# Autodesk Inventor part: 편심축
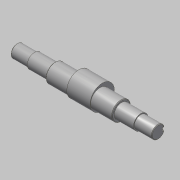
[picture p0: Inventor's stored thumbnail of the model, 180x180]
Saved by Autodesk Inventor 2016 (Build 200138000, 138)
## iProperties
Created: 2015-10
Part Number: 편심축
Document SubType Name: Modeling
Designer: mdu
Density: 7.86 g/cm^3
Material: 강철, 연강
Mass: 1327.93 g
Surface Area: 248.524 cm^2
Volume: 168.947 cm^3
Appearance: 강철
Author: mdu
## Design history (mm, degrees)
sketch "스케치1"
  geometry: L1 (-20.5, -41.331)-(-20.5, 32.669) reference; L2 (7.5, -30.031)-(7.5, 21.369) reference; L3 (135.5, -30.331)-(135.5, 21.669) reference; L4 (121.5, 21.369)-(121.5, -30.031) reference; L5 (184.5, -4.331)-(-57.5, -4.331); L6 (184.5, -4.331)-(184.5, 6.669); L7 (154.5, 8.169)-(121.5, 8.169); L8 (121.5, 8.169)-(121.5, 11.669); L9 (121.5, 11.669)-(7.5, 11.669); L10 (7.5, 11.669)-(7.5, 8.169); L11 (7.5, 8.169)-(-27.5, 8.169); L12 (-27.5, 8.169)-(-27.5, 6.669); L13 (-27.5, 6.669)-(-57.5, 6.669); L14 (-57.5, 6.669)-(-57.5, -4.331); L15 (154.5, 8.169)-(154.5, 6.669); L16 (154.5, 6.669)-(184.5, 6.669); C1 r 32.5 at (64.5, -4.331) reference; 1 further point
  constraints: 24 end point, 8 perpendicular, 5 point on line, 3 parallel, 2 collinear
  dimensions: "d1" = 25 diameter of L11 L5; "d2" = 32 diameter of L9 L5; "d3" = 22 diameter of L13 L5; "d4" = 35 distance of L10.end L11.end; "d5" = 30 distance of L12.end L13.end; "d15" = 33 distance of L7.start L7.end; "d26" = 30 distance of L15.end L6.end
revolve "회전1" sketch "스케치1" stored, may be unused: angle "d6" = 90 deg
node "작업 평면1"
sketch "스케치2"
  geometry: C1 r 16 at (0, 0) reference; C2 r 16 at (0, 0) reference; C3 r 20.75 at (0, 4); C4 r 16 at (0, 0) reference; 1 further point
  constraints: 1 centre point, 1 vertical alignment
  dimensions: "d8" = 41.5 diameter of C3; "d25" = 4 distance of C3.centre C1.centre
extrude "돌출1" join sketch "스케치2" stored distance "d9" = 40; taper "d10" = 0 deg
chamfer "모따기1" distance "d11" = 1; stored, may be unused: second distance "d12" = 2, angle "d13" = 45 deg
node "작업 평면2"
sketch "스케치3"
  geometry: L1 (-15, -10)-(-15, 10) reference; L2 (-15, 3)-(0, 3); L3 (0, -3)-(-15, -3); A1 r 3 centre (0, 0) between (0, -3) and (0, 3); 2 further points
  constraints: 4 end point, 2 perpendicular, 2 point on circle, 2 point on line, 2 tangent, 1 centre point, 1 horizontal alignment, 1 midpoint
  dimensions: "d16" = 18 dimension on A1 L1; "d17" = 6 distance between parallel lines of L3 L2
extrude "돌출2" cut sketch "스케치3" distance "d18" = 3.5; taper "d19" = 0 deg
node "작업 평면3"
node "솔리드1"
mirror "대칭1"
node "참조1"
node "참조2"
node "참조3"
node "참조4"
node "참조5"
node "투영된 루프1"
